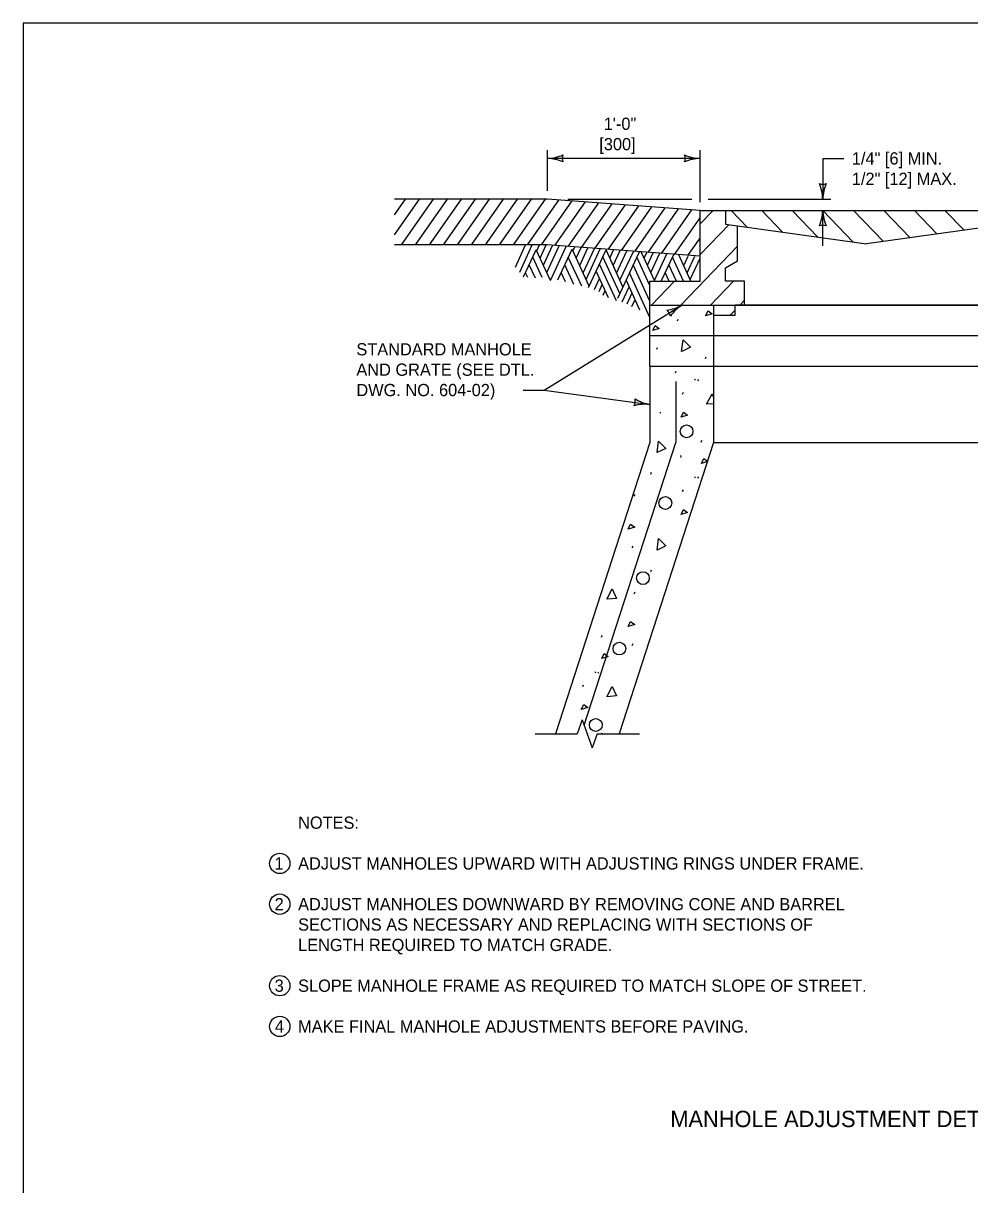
# Model space of a CAD drawing. Extents: x 49991.4 to 50021, y 49987.6 to 50011.4.
# Drawn here: x 50000.34 to 50004.98, y 50005.56 to 50011.26 of the extents above; entities that cross this region are included whole.
import ezdxf

# ---------------------------------------------------------------- set-up
doc = ezdxf.new("R2010")
doc.units = 0
for name, color, linetype in [('Level 1', 7, 'Continuous'), ('Level 2', 7, 'Continuous'), ('Level 3', 7, 'Continuous'), ('Level 4', 7, 'Continuous'), ('Level 6', 7, 'Continuous')]:
    doc.layers.add(name, color=color, linetype=linetype)

msp = doc.modelspace()

# ---------------------------------------------------------------- linework, layer by layer
at = {"layer": 'Level 1'}
for p, q in [((50002.9089, 50010.3995), (50002.1589, 50010.3995)), ((50002.1589, 50010.3222), (50002.213, 50010.3995)), ((50002.1589, 50010.2242), (50002.2817, 50010.3995)), ((50002.1928, 50010.1745), (50002.3504, 50010.3995)), ((50002.2615, 50010.1745), (50002.419, 50010.3995)), ((50002.3302, 50010.1745), (50002.4878, 50010.3995)), ((50002.3988, 50010.1745), (50002.5564, 50010.3995)), ((50002.4675, 50010.1745), (50002.6251, 50010.3995)), ((50002.5362, 50010.1745), (50002.6937, 50010.3995)), ((50002.6048, 50010.1745), (50002.7624, 50010.3995)), ((50002.6735, 50010.1745), (50002.831, 50010.3995)), ((50002.7422, 50010.1745), (50002.8997, 50010.3995)), ((50002.8108, 50010.1745), (50002.9656, 50010.3953)), ((50002.8796, 50010.1745), (50003.0307, 50010.3905)), ((50003.6589, 50010.3439), (50002.9089, 50010.3995)), ((50002.9462, 50010.1717), (50003.096, 50010.3856)), ((50003.0115, 50010.1668), (50003.1613, 50010.3808)), ((50003.0768, 50010.162), (50003.2265, 50010.376)), ((50003.142, 50010.1572), (50003.2919, 50010.3711)), ((50003.2073, 50010.1523), (50003.3571, 50010.3663)), ((50003.2726, 50010.1475), (50003.4225, 50010.3614)), ((50003.3379, 50010.1427), (50003.4877, 50010.3566)), ((50003.4032, 50010.1378), (50003.5529, 50010.3518)), ((50003.4684, 50010.133), (50003.6183, 50010.3469)), ((50003.5338, 50010.1282), (50003.6589, 50010.307)), ((50003.6589, 50009.9971), (50003.6589, 50010.3439)), ((50003.6589, 50010.3439), (50005.2912, 50010.3439)), ((50003.7228, 50010.3439), (50003.6589, 50010.2776)), ((50003.784, 50010.3439), (50003.784, 50010.2767)), ((50003.811, 50010.3439), (50003.8902, 50010.262)), ((50003.961, 50010.3439), (50004.0636, 50010.2374)), ((50004.111, 50010.3439), (50004.237, 50010.2131)), ((50004.261, 50010.3439), (50004.4107, 50010.1888)), ((50004.411, 50010.3439), (50004.5583, 50010.1912)), ((50004.561, 50010.3439), (50004.6903, 50010.2098)), ((50004.711, 50010.3439), (50004.8223, 50010.2284)), ((50004.861, 50010.3439), (50004.9543, 50010.247)), ((50003.8008, 50010.2743), (50003.6589, 50010.1276)), ((50003.784, 50010.2767), (50004.4752, 50010.1795)), ((50003.8431, 50010.0964), (50003.8431, 50010.2684)), ((50005.1661, 50010.2767), (50004.4752, 50010.1795)), ((50003.599, 50010.1233), (50003.6589, 50010.2088)), ((50002.9079, 50010.1745), (50002.1589, 50010.1745)), ((50002.7516, 50010.066), (50002.8017, 50010.1745)), ((50002.7733, 50010.0419), (50002.8349, 50010.1745)), ((50002.7917, 50010.0175), (50002.8542, 50010.1509)), ((50002.9235, 50010.0009), (50002.8542, 50010.1509)), ((50002.8565, 50010.1459), (50002.8695, 50010.1745)), ((50002.8731, 50010.11), (50002.9025, 50010.1745)), ((50002.8901, 50010.0749), (50002.9345, 50010.1725)), ((50002.9061, 50010.0391), (50002.9664, 50010.1702)), ((50003.6589, 50010.1189), (50002.9079, 50010.1745)), ((50003.6589, 50010.1189), (50002.9079, 50010.1745)), ((50002.9236, 50010.001), (50003.0009, 50010.1676)), ((50002.9598, 50010.0032), (50003.0302, 50010.1543)), ((50003.1145, 50009.972), (50003.0302, 50010.1542)), ((50003.0344, 50010.1451), (50003.0433, 50010.1645)), ((50003.051, 50010.1093), (50003.0751, 50010.1621)), ((50003.0676, 50010.0734), (50003.1071, 50010.1598)), ((50003.084, 50010.0379), (50003.1399, 50010.1573)), ((50003.1116, 50009.9656), (50003.1968, 50010.1502)), ((50003.1263, 50010.0631), (50003.1685, 50010.1552)), ((50003.28, 50009.9698), (50003.1968, 50010.1502)), ((50003.2154, 50010.11), (50003.2339, 50010.1504)), ((50003.2318, 50010.0738), (50003.2658, 50010.148)), ((50003.2489, 50010.0368), (50003.299, 50010.1455)), ((50003.254, 50009.9141), (50003.3604, 50010.141)), ((50003.2653, 50010.0014), (50003.3312, 50010.1432)), ((50003.4362, 50009.9971), (50003.37, 50010.1403)), ((50003.384, 50010.11), (50003.3968, 50010.1383)), ((50003.401, 50010.0749), (50003.4286, 50010.136)), ((50003.8431, 50010.1684), (50003.5644, 50009.8795)), ((50002.8827, 50010.0158), (50002.8371, 50010.1141)), ((50003.0778, 50009.9723), (50003.0116, 50010.1145)), ((50003.2476, 50009.9005), (50003.1651, 50010.081)), ((50003.2646, 50009.9369), (50003.1819, 50010.1165)), ((50003.4123, 50009.9756), (50003.348, 50010.1142)), ((50003.417, 50010.0391), (50003.4604, 50010.1336)), ((50003.4327, 50009.9971), (50003.4947, 50010.1311)), ((50003.4678, 50009.9971), (50003.529, 50010.1285)), ((50003.5772, 50009.9971), (50003.5225, 50010.1145)), ((50003.6138, 50009.9971), (50003.5538, 50010.1267)), ((50003.5785, 50010.0734), (50003.5998, 50010.1203)), ((50003.5949, 50010.038), (50003.6334, 50010.1203)), ((50003.6101, 50010.0052), (50003.6589, 50010.1095)), ((50003.784, 50010.0622), (50003.8431, 50010.0964)), ((50002.8124, 50010.0152), (50002.8017, 50010.0387)), ((50002.85, 50010.0111), (50002.8196, 50010.0772)), ((50002.998, 50009.9941), (50002.977, 50010.0398)), ((50003.039, 50009.9804), (50002.9941, 50010.0772)), ((50003.0993, 50010.0052), (50003.1263, 50010.0631)), ((50003.2085, 50009.9149), (50003.1487, 50010.046)), ((50003.4123, 50009.8186), (50003.3126, 50010.0387)), ((50003.4123, 50009.8988), (50003.3305, 50010.0772)), ((50003.5075, 50009.9971), (50003.4878, 50010.0399)), ((50003.5421, 50009.9971), (50003.505, 50010.0772)), ((50003.784, 50009.9971), (50003.784, 50010.0622)), ((50003.1398, 50009.9564), (50003.1647, 50010.0108)), ((50003.1629, 50009.9462), (50003.1786, 50009.9805)), ((50003.2768, 50009.8955), (50003.3109, 50009.9699)), ((50003.3633, 50009.8543), (50003.2957, 50010.0033)), ((50003.4123, 50009.8795), (50003.4123, 50009.9971)), ((50003.4123, 50009.9971), (50003.6589, 50009.9971)), ((50003.4126, 50009.8795), (50003.4126, 50009.9971)), ((50003.4126, 50009.9971), (50003.6589, 50009.9971)), ((50003.5332, 50009.9971), (50003.4198, 50009.8795)), ((50003.8224, 50009.9971), (50003.7093, 50009.8795)), ((50003.8767, 50009.9971), (50003.784, 50009.9971)), ((50003.8767, 50009.8795), (50003.8767, 50009.9971)), ((50003.182, 50009.9281), (50003.1923, 50009.9505)), ((50003.3007, 50009.8863), (50003.3248, 50009.9391)), ((50003.3239, 50009.8721), (50003.3396, 50009.9065)), ((50003.4126, 50009.8795), (50003.7252, 50009.8795)), ((50003.4126, 50009.7295), (50003.4126, 50009.8795)), ((50003.7252, 50009.8795), (50003.7252, 50009.2045)), ((50003.8302, 50009.8549), (50003.8065, 50009.8306)), ((50003.8302, 50009.8306), (50003.8302, 50009.8795)), ((50003.8302, 50009.8795), (50003.8767, 50009.8795)), ((50005.1202, 50009.8795), (50003.8302, 50009.8795)), ((50003.8767, 50009.9032), (50003.8539, 50009.8795)), ((50003.8767, 50009.8795), (50005.0734, 50009.8795)), ((50003.547, 50009.802), (50003.5508, 50009.811)), ((50003.7252, 50009.8306), (50003.8302, 50009.8306)), ((50005.5378, 50009.7295), (50003.4126, 50009.7295)), ((50003.4126, 50009.5795), (50003.4126, 50009.7295)), ((50003.4462, 50009.6625), (50003.4501, 50009.6715)), ((50003.6846, 50009.6172), (50003.6888, 50009.6262)), ((50003.4126, 50009.5795), (50003.4126, 50009.2045)), ((50003.4126, 50009.5795), (50005.5378, 50009.5795)), ((50003.5371, 50009.5467), (50003.541, 50009.5557)), ((50003.6313, 50009.5168), (50003.6352, 50009.5108)), ((50003.6466, 50009.5144), (50003.6505, 50009.5084)), ((50003.5398, 50009.5045), (50003.5398, 50009.2045)), ((50003.5722, 50009.4427), (50003.5764, 50009.4517)), ((50003.4603, 50009.3557), (50003.4642, 50009.3497)), ((50003.4126, 50009.2045), (50002.9482, 50007.7756)), ((50003.0893, 50007.8184), (50003.5398, 50009.2045)), ((50003.7252, 50009.2045), (50003.2608, 50007.7756)), ((50003.6634, 50009.2069), (50003.6676, 50009.2159)), ((50003.7252, 50009.2045), (50005.2252, 50009.2045)), ((50003.5632, 50009.1409), (50003.5641, 50009.1319)), ((50003.4165, 50009.05), (50003.4204, 50009.059)), ((50003.6313, 50009.0383), (50003.6352, 50009.0323)), ((50003.6466, 50009.0362), (50003.6505, 50009.0302)), ((50003.3355, 50008.9414), (50003.3394, 50008.9504)), ((50003.5722, 50008.9642), (50003.5764, 50008.9732)), ((50003.3256, 50008.6876), (50003.3295, 50008.6966)), ((50003.4165, 50008.5718), (50003.4204, 50008.5808)), ((50003.3355, 50008.4629), (50003.3394, 50008.4719)), ((50003.4603, 50008.399), (50003.4624, 50008.396)), ((50003.1738, 50008.2502), (50003.1777, 50008.2592)), ((50003.3256, 50008.2091), (50003.3295, 50008.2181)), ((50003.1414, 50008.0816), (50003.1453, 50008.0756)), ((50003.1567, 50008.0792), (50003.1606, 50008.0732)), ((50003.0826, 50008.0075), (50003.0865, 50008.0165)), ((50003.1756, 50007.7756), (50003.1777, 50007.7807))]:
    msp.add_line(p, q, dxfattribs=at)
msp.add_lwpolyline([(50008.6146, 50011.2628), (50000.3356, 50011.2628), (50000.3356, 50000.0624), (50008.6146, 50000.0624)], close=True, dxfattribs=at)
for points in [[(50003.6859, 50009.8263), (50003.6979, 50009.8512), (50003.718, 50009.8362), (50003.6859, 50009.8263)], [(50003.4264, 50009.7549), (50003.4384, 50009.7798), (50003.4582, 50009.7648), (50003.4264, 50009.7549)], [(50003.5677, 50009.6523), (50003.5755, 50009.7093), (50003.6112, 50009.6724), (50003.5686, 50009.6523)], [(50003.6904, 50009.3926), (50003.7174, 50009.4436), (50003.7252, 50009.4265)], [(50003.7252, 50009.3956), (50003.6916, 50009.3926)], [(50003.5653, 50009.3296), (50003.5773, 50009.3548), (50003.5974, 50009.3398), (50003.5653, 50009.3296)], [(50003.4471, 50009.1556), (50003.4549, 50009.2126), (50003.4906, 50009.1757), (50003.448, 50009.1559)], [(50003.6655, 50009.1019), (50003.6775, 50009.1268), (50003.6955, 50009.1136)], [(50003.6949, 50009.1112), (50003.6655, 50009.1019)], [(50003.5653, 50008.8514), (50003.5773, 50008.8763), (50003.5974, 50008.8613), (50003.5653, 50008.8514)], [(50003.3058, 50008.78), (50003.3178, 50008.8049), (50003.3376, 50008.7899), (50003.3058, 50008.78)], [(50003.4471, 50008.6774), (50003.4549, 50008.7344), (50003.4906, 50008.6975), (50003.448, 50008.6774)], [(50003.2008, 50008.4359), (50003.2275, 50008.4869), (50003.2485, 50008.4398), (50003.2017, 50008.4359)], [(50003.3058, 50008.3018), (50003.3178, 50008.3267), (50003.3376, 50008.3117), (50003.3058, 50008.3018)], [(50003.1756, 50008.1452), (50003.1876, 50008.1704), (50003.2077, 50008.1554), (50003.1756, 50008.1452)], [(50003.2008, 50007.9577), (50003.2275, 50008.0084), (50003.2485, 50007.9616), (50003.2017, 50007.9577)], [(50003.0754, 50007.8947), (50003.0874, 50007.9196), (50003.1075, 50007.9046), (50003.0754, 50007.8947)], [(50002.9647, 50007.7756), (50002.965, 50007.7777), (50002.9671, 50007.7756)]]:
    msp.add_lwpolyline(points, dxfattribs=at)
for centre in [(50003.5923, 50009.2599), (50003.4882, 50008.9084), (50003.378, 50008.5396), (50003.2625, 50008.1938), (50003.1467, 50007.8191)]:
    msp.add_circle(centre, 0.0313, dxfattribs=at)
at = {"layer": 'Level 2'}
for centre in [(50001.5952, 50007.1396), (50001.5952, 50006.9396), (50001.5952, 50006.5396), (50001.5952, 50006.3397)]:
    msp.add_circle(centre, 0.05, dxfattribs=at)
at = {"layer": 'Level 3'}
for p, q in [((50002.9089, 50010.4395), (50002.9089, 50010.6395)), ((50003.6589, 50010.5995), (50002.9089, 50010.5995)), ((50003.6589, 50010.3839), (50003.6589, 50010.6395)), ((50004.261, 50010.5995), (50004.3637, 50010.5995)), ((50004.261, 50010.5995), (50004.261, 50010.3995)), ((50003.0089, 50010.3995), (50003.6189, 50010.3995)), ((50003.6989, 50010.3995), (50004.301, 50010.3995)), ((50004.261, 50010.1705), (50004.261, 50010.3439)), ((50002.8925, 50009.4627), (50003.5689, 50009.8795)), ((50002.7898, 50009.4627), (50002.8925, 50009.4627)), ((50002.8925, 50009.4627), (50003.4126, 50009.392))]:
    msp.add_line(p, q, dxfattribs=at)
for centre, radius, start, end in [((50002.8974, 50010.8322), 0.233, 272.8273, 292.0772), ((50002.8997, 50010.3774), 0.2223, 67.456, 87.6395), ((50003.0371, 50010.5995), 0.0548, 162.1388, 197.8612), ((50003.6681, 50010.8216), 0.2223, 247.456, 267.6395), ((50003.5307, 50010.5995), 0.0548, 342.1388, 17.8612), ((50003.6704, 50010.3668), 0.233, 92.8273, 112.0772), ((50004.261, 50010.5277), 0.0548, 252.1388, 287.8612), ((50004.0283, 50010.388), 0.233, 2.8273, 22.0772), ((50004.4831, 50010.3903), 0.2223, 157.456, 177.6395), ((50004.0389, 50010.3531), 0.2223, 337.456, 357.6395), ((50004.4937, 50010.3554), 0.233, 182.8273, 202.0772), ((50004.261, 50010.2157), 0.0548, 72.1388, 107.8612), ((50003.4602, 50010.0734), 0.2223, 279.0975, 299.281), ((50003.4597, 50009.8122), 0.0548, 13.7803, 49.5027), ((50003.7008, 50009.6874), 0.233, 124.4688, 143.7187), ((50003.2856, 50009.4093), 0.0548, 334.3977, 10.1201), ((50003.4516, 50009.6109), 0.2223, 239.7149, 259.8984), ((50003.3926, 50009.1599), 0.233, 85.0862, 104.3361)]:
    msp.add_arc(centre, radius, start, end, dxfattribs=at)
at = {"layer": 'Level 4'}
msp.add_line((50003.7252, 50009.8795), (50003.8302, 50009.8795), dxfattribs=at)
at = {"layer": 'Level 6'}
for p, q in [((50003.0802, 50007.8442), (50003.0559, 50007.7756)), ((50003.0802, 50007.8442), (50003.1045, 50007.7756)), ((50002.8482, 50007.7756), (50003.0559, 50007.7756)), ((50003.1045, 50007.7756), (50003.1288, 50007.707)), ((50003.1531, 50007.7756), (50003.1288, 50007.707)), ((50003.1531, 50007.7756), (50003.3608, 50007.7756))]:
    msp.add_line(p, q, dxfattribs=at)

# ---------------------------------------------------------------- texts
at = {"layer": 'Level 2'}
for s, height, p in [('1\'-0"', 0.06, (50003.1856, 50010.7395)), ('[300]', 0.06, (50003.1638, 50010.6395)), ('1/4" [6] MIN.', 0.06, (50004.4037, 50010.5695)), ('1/2" [12] MAX.', 0.06, (50004.4037, 50010.4695)), ('STANDARD MANHOLE', 0.06, (50001.9713, 50009.6327)), ('AND GRATE (SEE DTL.', 0.06, (50001.9713, 50009.5327)), ('DWG. NO. 604-02)', 0.06, (50001.9713, 50009.4327)), ('NOTES:', 0.06, (50001.6852, 50007.3096)), ('1', 0.06, (50001.5691, 50007.1096)), ('ADJUST MANHOLES UPWARD WITH ADJUSTING RINGS UNDER FRAME.', 0.06, (50001.6852, 50007.1096)), ('2', 0.06, (50001.57, 50006.9096)), ('ADJUST MANHOLES DOWNWARD BY REMOVING CONE AND BARREL', 0.06, (50001.6852, 50006.9096)), ('SECTIONS AS NECESSARY AND REPLACING WITH SECTIONS OF', 0.06, (50001.6852, 50006.8096)), ('LENGTH REQUIRED TO MATCH GRADE.', 0.06, (50001.6852, 50006.7096)), ('3', 0.06, (50001.57, 50006.5096)), ('SLOPE MANHOLE FRAME AS REQUIRED TO MATCH SLOPE OF STREET.', 0.06, (50001.6852, 50006.5096)), ('4', 0.06, (50001.5712, 50006.3097)), ('MAKE FINAL MANHOLE ADJUSTMENTS BEFORE PAVING.', 0.06, (50001.6852, 50006.3096)), ('MANHOLE ADJUSTMENT DETAIL', 0.08, (50003.5125, 50005.8456))]:
    msp.add_text(s, height=height, dxfattribs=at).set_placement(p)

doc.saveas('drawing.dxf')
